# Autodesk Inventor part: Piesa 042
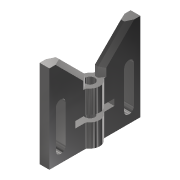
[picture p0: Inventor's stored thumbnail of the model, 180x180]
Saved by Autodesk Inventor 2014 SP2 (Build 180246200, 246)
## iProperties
Created: 2009-01
Part Number: Piesa 042
Document SubType Name: Modeling
Designer: Costel
Material: Steel
Density: 7.85 g/cm^3
Appearance: Steel - Polished
Mass: 102.825 g
Surface Area: 74.457 cm^2
Volume: 13.0988 cm^3
Author: Costel
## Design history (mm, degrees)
sketch "Sketch2"
  geometry: L1 (-4, 38)-(-4, 32); L2 (-4, 32)-(4, 32); L3 (4, 38)-(4, 32); L4 (-28, 0)-(-28, 54); L5 (-33.6, 0)-(44.8, 0); L6 (-28, 0)-(28, 0); L7 (-20, 54)-(-4, 38); L8 (18, 31)-(18, 8); L9 (24, 31)-(24, 8); L10 (28, 0)-(28, 54); L11 (-28, 54)-(-20, 54); L12 (20, 54)-(4, 38); L13 (28, 54)-(20, 54); L14 (-18, 31)-(-18, 8); L15 (-24, 31)-(-24, 8); A1 r 3 centre (21, 8) between (18, 8) and (24, 8); A2 r 3 centre (21, 31) between (24, 31) and (18, 31); A3 r 3 centre (-21, 8) between (-24, 8) and (-18, 8); A4 r 3 centre (-21, 31) between (-18, 31) and (-24, 31)
  constraints: 30 end point, 8 point on circle, 4 centre point, 3 parallel, 3 tangent, 2 perpendicular, 1 collinear, 1 equal radius, 1 vertical, 1 vertical alignment
  dimensions: "d0" = 8 distance between parallel lines of L3 L1; "d1" = 90 deg angle of L12 L7; "d2" = 56 distance between parallel lines of L10 L4; "d3" = 54 distance between parallel lines of L6 L11; "d4" = 32 distance between parallel lines of L5 L2; "d5" = 40 distance of L12.start L7.start; "d6" = 42 distance of A1.centre A3.centre; "d7" = 8 distance from line of L6 A3.centre; "d8" = 23 distance of A4.centre A3.centre; "d52" = 3 radius of A4; "d53" = 3 radius of A1
extrude "Extrusion1" new body sketch "Sketch2" stored distance "d9" = 6; taper "d10" = 0 deg
chamfer "Chamfer1" distance "d11" = 2; stored, may be unused: second distance "d12" = 3, angle "d13" = 45 deg
chamfer "Chamfer2" distance "d14" = 2; stored, may be unused: second distance "d15" = 3, angle "d16" = 45 deg
chamfer "Chamfer3" distance "d17" = 2; stored, may be unused: second distance "d18" = 3, angle "d19" = 45 deg
chamfer "Chamfer4" distance "d20" = 2; stored, may be unused: second distance "d21" = 3, angle "d22" = 45 deg
chamfer "Chamfer5" distance "d23" = 2; stored, may be unused: second distance "d24" = 3, angle "d25" = 45 deg
chamfer "Chamfer6" distance "d26" = 2; stored, may be unused: second distance "d27" = 3, angle "d28" = 45 deg
chamfer "Chamfer7" distance "d29" = 2; stored, may be unused: second distance "d30" = 3, angle "d31" = 45 deg
chamfer "Chamfer8" distance "d32" = 2; stored, may be unused: second distance "d33" = 3, angle "d34" = 45 deg
sketch "Sketch3"
  geometry: L1 (-7.2, 0)-(9.6, 0) reference; L2 (0, -7.2)-(0, 9.6) reference; C1 r 6 at (0, 0)
  constraints: 2 point on line, 1 centre point
  dimensions: "d35" = 12 diameter of C1
extrude "Extrusion2" join sketch "Sketch3" distance "d36" = 32; taper "d37" = 0 deg
hole "Hole1" diameter "d45" = 6; stored, may be unused: countersink angle "d49" = 90 deg, drill point angle "d51" = 118 deg; dims "d43" = 10, "d44" = 10, "d46" = 6, "d47" = 4, "d48" = 2, "d50" = 8
sketch "Sketch5"
  geometry: L1 (6, 0)-(6, 32) reference; L2 (-6, 0)-(-6, 32) reference; L3 (-6, 0)-(-3, 0) reference; L4 (6, 18)-(-6, 18); L5 (-6, 18)-(-6, 14); L6 (-6, 14)-(6, 14); L7 (6, 14)-(6, 18)
  constraints: 8 end point, 2 parallel, 2 point on line, 1 horizontal, 1 perpendicular
  dimensions: "d54" = 14 distance between parallel lines of L3 L6; "d55" = 4 distance between parallel lines of L6 L4
extrude "Extrusion4" cut sketch "Sketch5" stored distance "d56" = 24; taper "d57" = 0 deg
fillet "Fillet1" dims "d58" = 2
body "Solid1"
